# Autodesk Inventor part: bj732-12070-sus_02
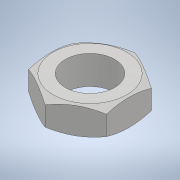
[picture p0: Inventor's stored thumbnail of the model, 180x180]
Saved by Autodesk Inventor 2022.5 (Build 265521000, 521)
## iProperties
Part Number: bj732-12070-sus_02
Material: 一般
Document SubType Name: Modeling
Designer: ImaoCorp
Density: 1 g/cm^3
Appearance: 既定
Author: ImaoCorp
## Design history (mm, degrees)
feature "bj732-12070-sus_02"
node "ソリッド1"
